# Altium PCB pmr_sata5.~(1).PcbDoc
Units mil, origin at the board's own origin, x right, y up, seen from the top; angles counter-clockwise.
Board outline 5317 x 3934 mil, 2 copper layers (Top Layer, Bottom Layer); 9 components, 33 nets, 133 pads, 0 vias.
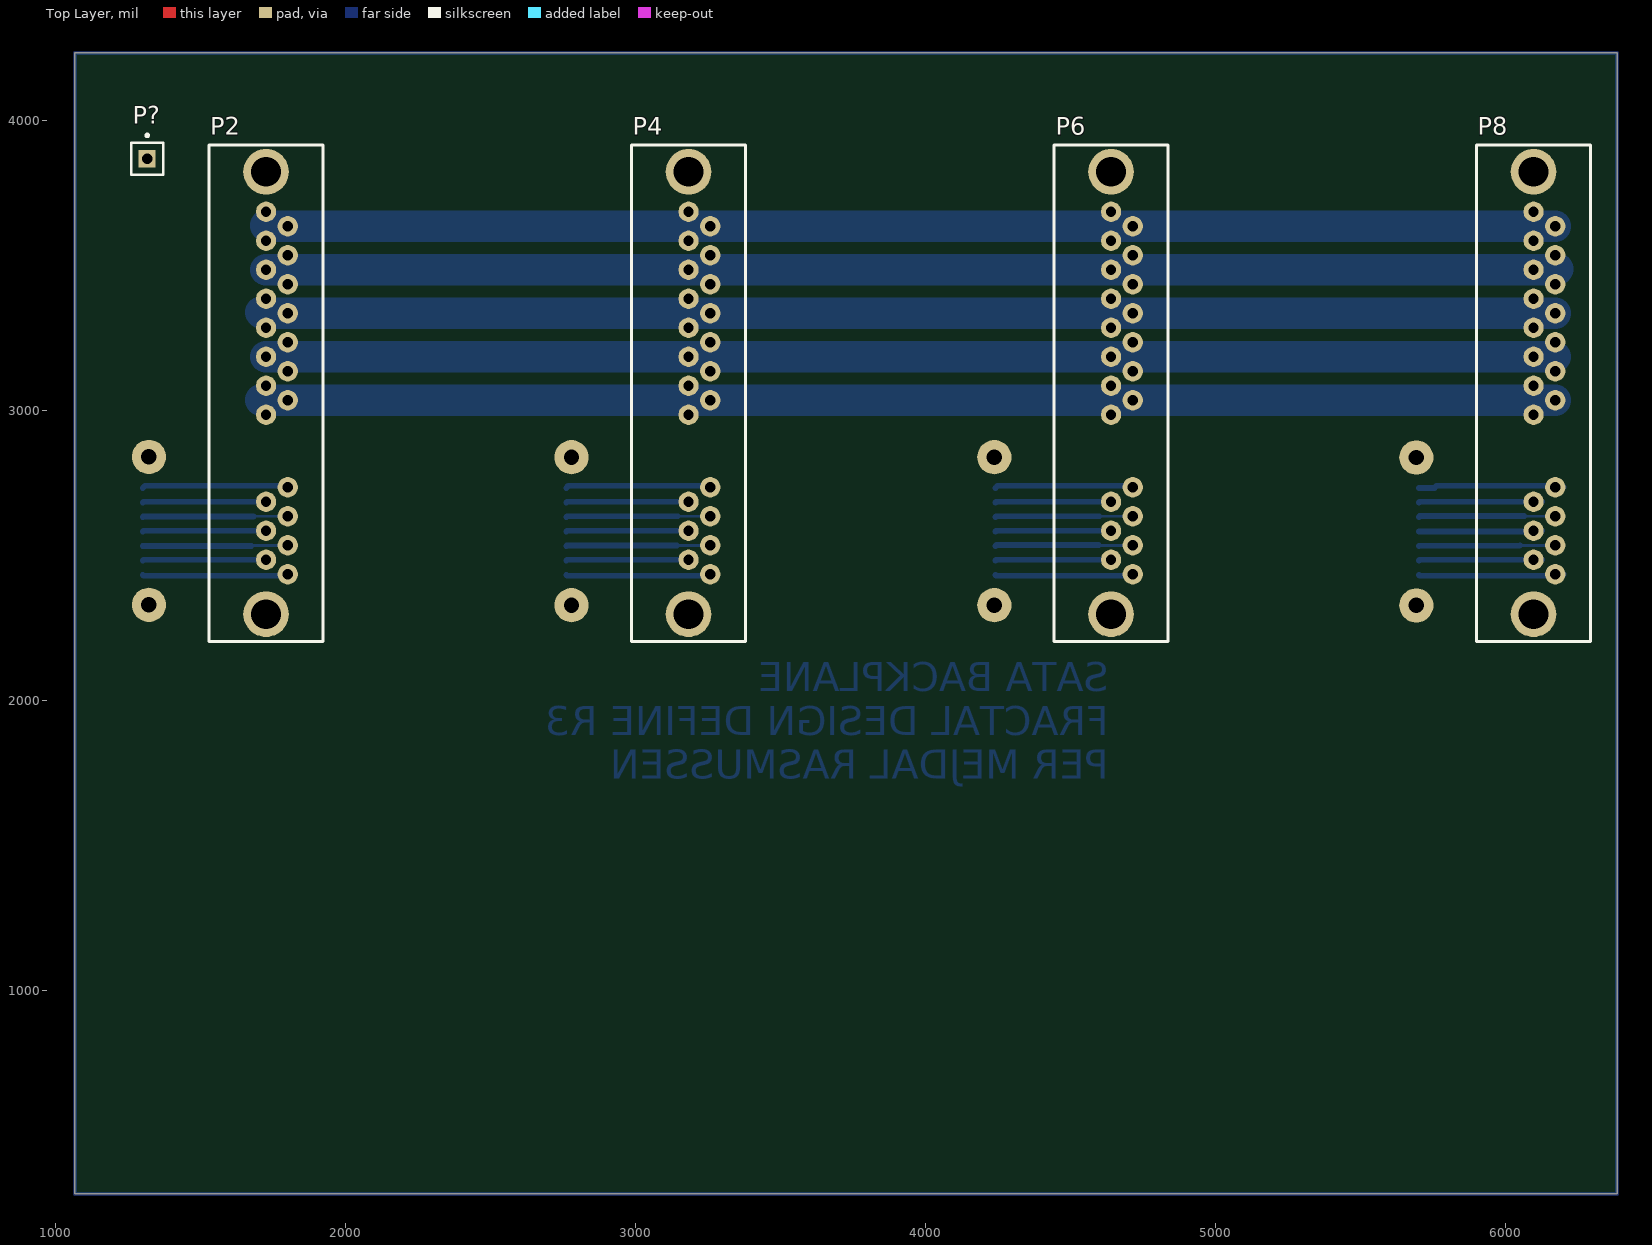
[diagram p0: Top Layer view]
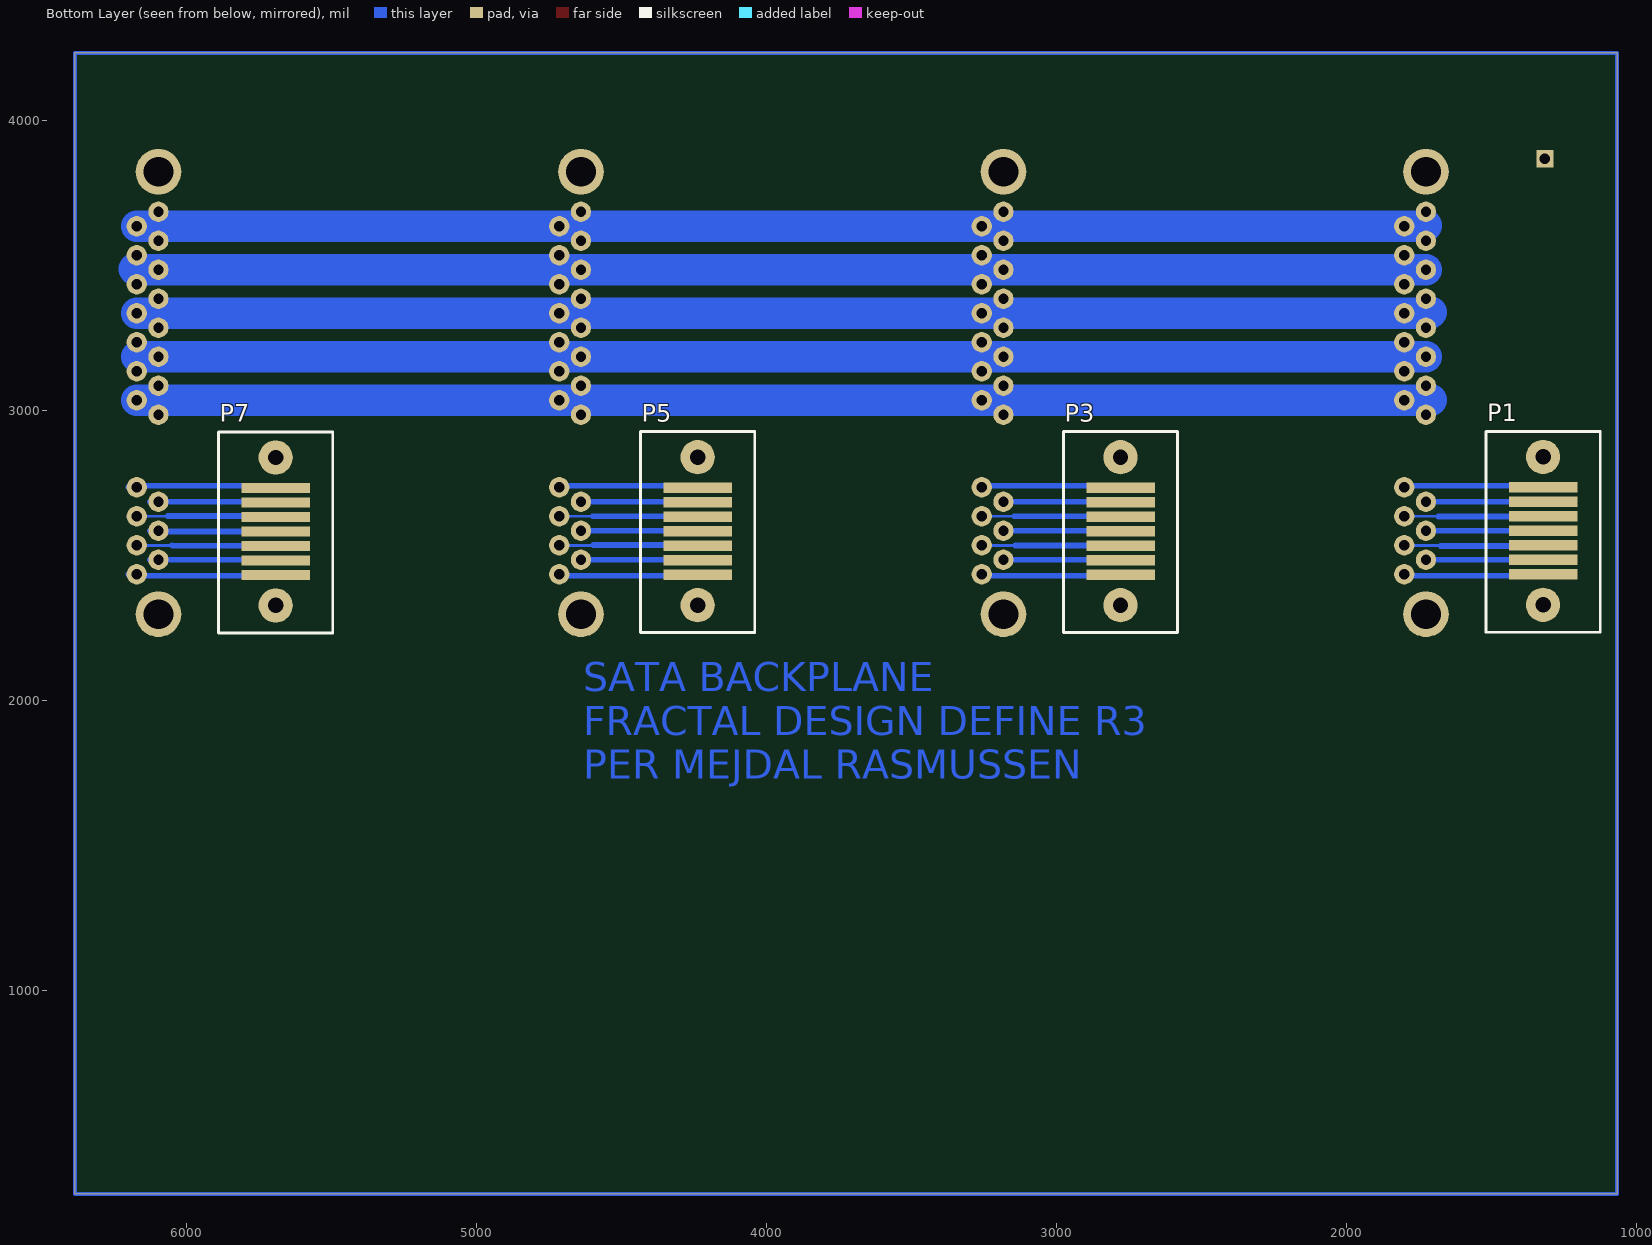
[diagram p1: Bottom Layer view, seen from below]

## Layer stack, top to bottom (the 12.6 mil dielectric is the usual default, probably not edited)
Top Solder: solder mask 0.4, Solder Resist, Dk 3.5
Top Layer: signal copper 1.4
Dielectric1: dielectric 12.6, FR-4, Dk 4.8
Bottom Layer: signal copper 1.4
Bottom Solder: solder mask 0.4, Solder Resist, Dk 3.5

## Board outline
1067,300 6384,300 6384,4234 1067,4234

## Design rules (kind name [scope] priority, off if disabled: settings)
Clearance [All] p1: gap=10
PolygonConnect [All] p1: connectstyle=Relief reliefconductorwidth=10 reliefentries=4 polygonreliefangle="90 Angle" airgapwidth=10
RoomDefinition pmr_sata [InComponentClass('pmr_sata')] p1 off: confinementstyle=ConfineIn formatcopy=TRUE lockcomponents=FALSE outline 7570,1160 7280,1160 7280,1590 7570,1590
RoutingVias [All] p1: holewidth=28 width=50 viastyle="Through Hole" minholewidth=28 minwidth=50 maxholewidth=28 maxwidth=50
SilkToSolderMaskClearance SilkscreenOverComponentPads [IsPad] p1: minsilkscreentomaskgap=10 clearancetoexposedcopper=TRUE
SolderMaskExpansion [All] p1: expansion=4
Width [All] p1: maxlimit=500 minlimit=10 preferedwidth=10
29 further rules are at their usual default settings.

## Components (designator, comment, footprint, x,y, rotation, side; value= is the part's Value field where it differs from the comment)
P1 "SATA lille" "pmr_sata -lille" 1322,2331 r90 bottom
P2 "SATA STOR" pmr_sata 1726,2299 r90 top
P3 "SATA lille" "pmr_sata -lille" 2779,2330 r90 bottom
P4 "SATA STOR" pmr_sata 3182.7,2299 r90 top
P5 "SATA lille" "pmr_sata -lille" 4237,2330 r90 bottom
P6 "SATA STOR" pmr_sata 4639.4,2299 r90 top
P7 "SATA lille" "pmr_sata -lille" 5692,2329 r90 bottom
P8 "SATA STOR" pmr_sata 6096.1,2299 r90 top
P? "Plug" PIN1 1316,3869 r0 top

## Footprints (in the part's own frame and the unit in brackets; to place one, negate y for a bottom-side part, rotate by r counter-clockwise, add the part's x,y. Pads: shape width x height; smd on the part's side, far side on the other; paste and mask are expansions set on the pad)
PIN1 [mm] "Connector; Plug"
  rect 1.5x1.5 hole 0.9: 1(0,0)
  silkscreen extent -1.4,-1.4 1.4,2.17
pmr_sata [mm]
  round 1.778 hole 0.9: P1(17.46,0) P2(18.73,-1.9) P3(20,0) P4(21.27,-1.9) P5(22.54,0) P6(23.81,-1.9) P7(25.08,0) P8(26.35,-1.9) P9(27.62,0) P10(28.89,-1.9) P11(30.16,0) P12(31.43,-1.9) P13(32.7,0) P14(33.97,-1.9) P15(35.24,0) S1(3.49,-1.9) S2(4.76,0) S3(6.03,-1.9) S4(7.3,0) S5(8.57,-1.9) S6(9.84,0) S7(11.11,-1.9)
  round 4 hole 2.6: S8(0,0) S8(38.74,0)
  silkscreen extent -2.4,-5 41.1,5
"pmr_sata -lille" [mm]
  rect 0.9x6 smd: S1(2.67,0) S2(3.94,0) S3(5.21,0) S4(6.48,0) S5(7.75,0) S6(9.02,0) S7(10.29,0)
  round 3 hole 1.35: S8(0,0) S8(12.96,0)
  silkscreen extent -2.4,-5 15.2,5

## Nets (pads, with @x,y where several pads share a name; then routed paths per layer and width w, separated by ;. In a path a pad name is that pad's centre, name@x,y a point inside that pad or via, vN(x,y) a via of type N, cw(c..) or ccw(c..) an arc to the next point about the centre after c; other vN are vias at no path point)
GND1: P2.P4 P2.P5 P2.P6 P4.P4 P4.P5 P4.P6 P6.P4 P6.P5 P6.P6 P8.P4 P8.P5 P8.P6 | length 4444
  Bottom Layer w110: P2.P5 3192.54,3186.4 4659.07,3186.4 6170,3186.4
GND2: P2.P10 P2.P11 P2.P12 P4.P10 P4.P11 P4.P12 P6.P10 P6.P11 P6.P12 P8.P10 P8.P11 P8.P12 | length 4454.1
  Bottom Layer w110: P2.P11 P8.P11 6176.4,3486.4 6179,3489
NetP1_S1: P1.S1 P2.S1 | length 503
  Bottom Layer w20: P1.S1@1301,2434.12 1303.72,2431.4 1795.8,2431.4 P2.S1
NetP1_S2: P1.S2 P2.S2 | length 425.9
  Bottom Layer w20: P1.S2@1301,2484.12 1303.28,2486.4 P2.S2
NetP1_S3: P1.S3 P2.S3 | length 500.8
  Bottom Layer w10: 1675,2534 1677.4,2536.4 P2.S3
  Bottom Layer w20: P1.S3@1301,2534.12 1301.12,2534 1675,2534
NetP1_S4: P1.S4 P2.S4 | length 425.9
  Bottom Layer w20: P1.S4@1301,2584.12 1303.28,2586.4 P2.S4
NetP1_S5: P1.S5 P2.S5 | length 526.2
  Bottom Layer w10: 1683,2636 1683.4,2636.4 P2.S5
  Bottom Layer w15: P2.S5@1776,2638 1777.6,2636.4 P2.S5
  Bottom Layer w20: P1.S5@1301,2634.12 1302.88,2636 1683,2636
NetP1_S6: P1.S6 P2.S6 | length 425.9
  Bottom Layer w20: P1.S6@1301,2684.12 1303.28,2686.4 P2.S6
NetP1_S7: P1.S7 P2.S7 | length 504.9
  Bottom Layer w20: P1.S7@1301,2734.12 1308.28,2741.4 1795.8,2741.4 P2.S7
NetP3_S1: P3.S1 P4.S1 | length 509.5
  Bottom Layer w20: P3.S1@2761,2434.12 2763.72,2431.4 3262.34,2431.4 P4.S1@3267.34,2436.4
NetP3_S2: P3.S2 P4.S2 | length 432.5
  Bottom Layer w20: P3.S2@2761,2484.12 2763.28,2486.4 P4.S2@3192.54,2486.4
NetP3_S3: P3.S3 P4.S3 | length 507.3
  Bottom Layer w10: 3142,2536 3142.4,2536.4 P4.S3@3267.34,2536.4
  Bottom Layer w20: P3.S3@2761,2534.12 2762.88,2536 3142,2536
NetP3_S4: P3.S4 P4.S4 | length 432.5
  Bottom Layer w20: P3.S4@2761,2584.12 2763.28,2586.4 P4.S4@3192.54,2586.4
NetP3_S5: P3.S5 P4.S5 | length 507.3
  Bottom Layer w10: 3145.4,2636.4 P4.S5@3267.34,2636.4
  Bottom Layer w20: P3.S5@2761,2634.12 2763.28,2636.4 3145.4,2636.4
NetP3_S6: P3.S6 P4.S6 | length 432.5
  Bottom Layer w20: P3.S6@2761,2684.12 2763.28,2686.4 P4.S6@3192.54,2686.4
NetP3_S7: P3.S7 P4.S7 | length 511.4
  Bottom Layer w20: P3.S7@2761,2734.12 2768.28,2741.4 3262.34,2741.4 P4.S7@3267.34,2736.4
NetP5_S1: P5.S1 P6.S1 | length 496.1
  Bottom Layer w20: P5.S1@4241,2434.12 4243.72,2431.4 4728.87,2431.4 P6.S1@4733.87,2436.4
NetP5_S2: P5.S2 P6.S2 | length 419
  Bottom Layer w20: P5.S2@4241,2484.12 4243.28,2486.4 P6.S2@4659.07,2486.4
NetP5_S3: P5.S3 P6.S3 | length 494.3
  Bottom Layer w10: 4597,2536.4 P6.S3@4733.87,2536.4
  Bottom Layer w20: P5.S3@4241,2534.12 4243.88,2537 4596.4,2537 4597,2536.4
NetP5_S4: P5.S4 P6.S4 | length 419
  Bottom Layer w20: P5.S4@4241,2584.12 4243.28,2586.4 P6.S4@4659.07,2586.4
NetP5_S5: P5.S5 P6.S5 | length 477.2
  Bottom Layer w10: 4599,2636.4 P6.S5@4717.28,2636.4
  Bottom Layer w20: P5.S5@4241,2634.12 4243.28,2636.4 4599,2636.4
NetP5_S6: P5.S6 P6.S6 | length 419
  Bottom Layer w20: P5.S6@4241,2684.12 4243.28,2686.4 P6.S6@4659.07,2686.4
NetP5_S7: P5.S7 P6.S7 | length 498
  Bottom Layer w20: P5.S7@4241,2734.12 4248.28,2741.4 4728.87,2741.4 P6.S7@4733.87,2736.4
NetP7_S1: P7.S1 P8.S1 | length 502.6
  Bottom Layer w20: P7.S1@5701,2434.12 5703.72,2431.4 6195.41,2431.4 P8.S1@6200.41,2436.4
NetP7_S2: P7.S2 P8.S2 | length 425.6
  Bottom Layer w20: P7.S2@5701,2484.12 5703.28,2486.4 P8.S2@6125.61,2486.4
NetP7_S3: P7.S3 P8.S3 | length 500.4
  Bottom Layer w10: 6049,2536.4 P8.S3@6200.41,2536.4
  Bottom Layer w20: P7.S3@5701,2534.12 5701.88,2535 6047.6,2535 6049,2536.4
NetP7_S4: P7.S4 P8.S4 | length 425.6
  Bottom Layer w20: P7.S4@5701,2584.12 6123.32,2584.12 P8.S4@6125.61,2586.4
NetP7_S5: P7.S5 P8.S5 | length 500.9
  Bottom Layer w10: 6064,2636.4 P8.S5@6200.41,2636.4
  Bottom Layer w20: P7.S5@5701,2634.12 5703.88,2637 6063.4,2637 6064,2636.4
NetP7_S6: P7.S6 P8.S6 | length 425.6
  Bottom Layer w20: P7.S6@5701,2684.12 5703.28,2686.4 P8.S6@6125.61,2686.4
NetP7_S7: P7.S7 P8.S7 | length 504.5
  Bottom Layer w20: P7.S7@5701,2734.12 5754.28,2734.12 5761.57,2741.4 6195.41,2741.4 P8.S7@6200.41,2736.4
VCC1: P2.P1 P2.P2 P2.P3 P4.P1 P4.P2 P4.P3 P6.P1 P6.P2 P6.P3 P8.P1 P8.P2 P8.P3 | length 4483.2
  Bottom Layer w110: 1708,3038 1709.6,3036.4 P2.P2 3267.34,3036.4 P6.P2 ; P6.P2@4733.87,3036.4 P6.P2 ; P8.P2 P6.P2
VCC2: P2.P7 P2.P8 P2.P9 P4.P7 P4.P8 P4.P9 P6.P7 P6.P8 P6.P9 P8.P7 P8.P8 P8.P9 | length 4464.4
  Bottom Layer w110: 1708,3340 1711.6,3336.4 P2.P8 3267.34,3336.4 4733.87,3336.4 P8.P8
VCC3: P2.P13 P2.P14 P2.P15 P4.P13 P4.P14 P4.P15 P6.P13 P6.P14 P6.P15 P8.P13 P8.P14 P8.P15 | length 4466.7
  Bottom Layer w110: 1725,3639 1727.6,3636.4 P2.P14 3267.34,3636.4 P6.P14@4733.87,3636.4 ; P6.P14 5696.6,3636.4 P8.P14
pads on no net: P1.S8 P2.S8 P3.S8 P4.S8 P5.S8 P6.S8 P7.S8 P8.S8 P?.1
copper on no net: | length 18502
  Bottom Layer w15: 1067,300 6384,300 6384,4234 1067,4234 1067,300

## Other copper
Bottom Layer:
  text "SATA BACKPLANE" at 4632,2033 h100
  text "FRACTAL DESIGN DEFINE R3" at 4632,1882 h100
  text "PER MEJDAL RASMUSSEN" at 4632,1731 h100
